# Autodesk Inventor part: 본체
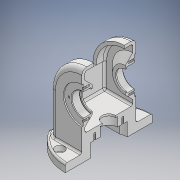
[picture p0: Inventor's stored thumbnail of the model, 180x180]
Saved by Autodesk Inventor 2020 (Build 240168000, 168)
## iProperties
Created: 2024-08
Part Number: 본체
Material: 일반
Document SubType Name: Modeling
Designer: 1강의실14
Density: 1 g/cm^3
Appearance: 기본값
Author: 1강의실14
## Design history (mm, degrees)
sketch "스케치1"
  geometry: L1 (-51, 0)-(-51, -81); L2 (-51, -81)-(51, -81); L3 (51, -81)-(51, 0); A1 r 51 centre (0, 0) between (-51, 0) and (51, 0); 1 further point
  constraints: 6 end point, 2 point on circle, 1 centre point, 1 coincident, 1 perpendicular, 1 tangent, 1 vertical
  dimensions: "d0" = 102 diameter of A1; "d1" = 81 distance of L1.start L1.end; "d2" = 102 distance of L1.end L2.end; "d3" = 81 distance from line of L2 point (0, 0)
extrude "돌출1" new body sketch "스케치1" stored distance "d4" = 88; taper "d5" = 0 deg
sketch "스케치2"
  geometry: L1 (51, 25)-(0, 25); L2 (0, 25)-(0, -25); L3 (0, -25)-(51, -25); L4 (51, -25)-(51, 25); L5 (-10.2, 0)-(61.2, 0) reference; 1 further point
  constraints: 8 end point, 2 parallel, 1 horizontal, 1 perpendicular, 1 other
  dimensions: "d6" = 51 distance of L3.end L2.end; "d7" = 50 distance of L2.end L1.end; "d8" = 0 distance from line of point (0, 0) L2
extrude "돌출2" cut sketch "스케치2" extent not by distance; stored distance "d9" = 51; taper "d10" = 0 deg
sketch "스케치3"
  geometry: C1 r 30 at (0, 0); C2 r 18.5 at (0, 0); C3 r 16 at (0, 0); 1 further point
  constraints: 3 centre point, 3 coincident
  dimensions: "d11" = 60 diameter of C1; "d12" = 37 diameter of C2; "d13" = 32 diameter of C3
extrude "돌출3" cut sketch "스케치3" distance "d14" = 2; taper "d15" = 0 deg
extrude "돌출4" cut sketch "스케치3" distance "d16" = 15; taper "d17" = 0 deg
extrude "돌출5" cut sketch "스케치3" extent not by distance; stored distance "d18" = 0; taper "d19" = 0 deg
sketch "스케치4"
  geometry: C1 r 30 at (0, 0); C2 r 30 at (0, 0) reference; C3 r 18.5 at (0, 0); 1 further point
  constraints: 2 centre point, 2 coincident
  dimensions: "d20" = 60 diameter of C1; "d21" = 37 diameter of C3
extrude "돌출6" cut sketch "스케치4" distance "d22" = 2; taper "d23" = 0 deg
extrude "돌출7" cut sketch "스케치4" distance "d24" = 15; taper "d25" = 0 deg
node "작업 평면1"
sketch "스케치5"
  geometry: L1 (46, -39)-(-41, -39); L2 (-41, -39)-(-41, 39); L3 (-41, 39)-(46, 39); L4 (46, 39)-(46, -39); L5 (51, -44)-(51, -25) reference; L6 (51, -44)-(51, 43.976); L7 (46, 0)-(0, 0); L8 (33.5, -39)-(33.5, -27); L9 (0, -25)-(51, -25) reference; L10 (33.5, -27)-(-35.015, -27); L11 (-33.5, -39)-(-21.5, -27); L12 (-33.5, -39)-(-7.367, -39); L13 (33.5, 39)-(33.5, 27); L14 (33.5, 27)-(-29.081, 27); L15 (-33.5, 39)-(-21.5, 27); L16 (-33.5, 39)-(-9.579, 39); L17 (33.5, 39)-(10.052, 15.552); L18 (33.5, 39)-(66.661, 39); L19 (33.5, -39)-(10.052, -15.552); L20 (33.5, -39)-(66.661, -39); L21 (0, 0)-(0, 27); L22 (0.5, 27)-(0.5, -27); L23 (-81, -44)-(-81, 44) reference; L24 (0, 25)-(0, 25) reference; L25 (0, 25)-(0, 44) reference; L26 (0, 44)-(0, 44) reference; L27 (0, 44)-(0, 25) reference; L28 (51, 44)-(0, 44) reference; 4 further points
  constraints: 40 end point, 10 point on line, 7 horizontal, 6 perpendicular, 2 equal length, 2 parallel, 1 midpoint, 1 vertical
  dimensions: "d27" = 5 distance between parallel lines of L4 L6; "d28" = 78 distance between parallel lines of L3 L1; "d29" = 12 distance of L8.start L8.end; "d30" = 33.5 distance from line of L7.end L8; "d32" = 45 deg angle of L12 L11; "d33" = 12 distance of L13.start L13.end; "d34" = 45 deg angle of L15 L16; "d35" = 33.5 distance from line of L7.end L13; "d36" = 135 deg angle of L17 L18; "d37" = 135 deg angle of L20 L19; "d38" = 33.5 horizontal distance of L11.start L7.end; "d39" = 33.5 horizontal distance of L15.start L7.end; "d88" = 40 distance between parallel lines of L23 L2; "d89" = 45.5 distance between parallel lines of L22 L4; "d145" = 33.16071 distance of L8.start L20.end; "d146" = 33.16071 distance of L13.start L18.end; "d147" = 5 distance between parallel lines of L3 L28 (derived)
  node "투영된 루프1"
sketch "스케치6"
  geometry: L1 (-72, 0)-(-16, 0); L2 (-16, 0)-(-16, 19); L3 (-16, 19)-(-72, 19); L4 (-72, 19)-(-72, 0); L5 (-88, 0)-(0, 0) reference; L6 (-69, 81)-(-19, 81) reference; 5 further points
  constraints: 8 end point, 4 midpoint, 2 parallel, 1 coincident, 1 horizontal, 1 perpendicular, 1 vertical alignment
  dimensions: "d40" = 56 distance of L3.end L2.end; "d41" = 19 distance of L2.end L1.end
extrude "돌출8" cut sketch "스케치6" extent not by distance; stored distance "d42" = 0; taper "d43" = 0 deg
node "작업 평면2"
sketch "스케치7"
  geometry: C1 r 30 at (0, 0); C2 r 14 at (0, 0); C3 r 11 at (0, 0); 1 further point
  constraints: 3 centre point, 3 coincident
  dimensions: "d45" = 60 diameter of C1; "d46" = 28 diameter of C2; "d47" = 22 diameter of C3
extrude "돌출9" cut sketch "스케치7" distance "d48" = 22; taper "d49" = 0 deg
extrude "돌출10" cut sketch "스케치7" distance "d50" = 37; taper "d51" = 0 deg
extrude "돌출11" cut sketch "스케치7" extent not by distance; stored distance "d52" = 69.381; taper "d53" = 0 deg
sketch "스케치9"
  geometry: C1 r 11 at (0, 0) reference; C2 r 71 at (0, 0); 1 further point
  constraints: 1 centre point, 1 coincident
  dimensions: "d55" = 142 diameter of C2
extrude "돌출12" join sketch "스케치9" distance "d56" = 13; taper "d57" = 0 deg
sketch "스케치8"
  geometry: L1 (-51, -81)-(51, -81) reference; 2 further points
  constraints: 1 vertical alignment, 1 other
  dimensions: "d54" = 30 distance from line of L1 point (0, -51)
sketch "스케치10"
  geometry: L1 (-80, 28)-(80, 28); L2 (80, 28)-(80, -28); L3 (80, -28)-(-80, -28); L4 (-80, -28)-(-80, 28); L5 (-80, 28)-(80, -28); L6 (80, 28)-(-80, -28); 1 further point
  constraints: 12 end point, 2 midpoint, 2 parallel, 1 horizontal, 1 perpendicular
  dimensions: "d58" = 56 distance of L1.end L2.end; "d59" = 80 distance from line of point (0, 0) L2
extrude "돌출13" cut sketch "스케치10" distance "d60" = 13; taper "d61" = 0 deg
extrude "돌출14" cut sketch "스케치7" distance "d62" = 22; taper "d63" = 0 deg
sketch "스케치11"
  geometry: C1 r 7.5 at (25, 55); C2 r 4.5 at (25, 55); C3 r 7.5 at (-25, 55); C4 r 4.5 at (-25, 55); C5 r 7.5 at (25, -55); C6 r 4.5 at (25, -55); C7 r 7.5 at (-25, -55); C8 r 4.5 at (-25, -55); 1 further point
  constraints: 8 centre point, 4 coincident, 2 horizontal alignment, 2 vertical alignment
  dimensions: "d64" = 15 diameter of C1; "d65" = 9 diameter of C2; "d66" = 15 diameter of C3; "d67" = 9 diameter of C4; "d68" = 15 diameter of C5; "d69" = 9 diameter of C6; "d70" = 15 diameter of C7; "d71" = 9 diameter of C8; "d72" = 110 distance of C5.centre C1.centre; "d73" = 50 distance of C3.centre C1.centre; "d74" = 55 vertical distance of point (0, 0) C1.centre; "d75" = 25 horizontal distance of point (0, 0) C3.centre
extrude "돌출15" cut sketch "스케치11" distance "d76" = 8.8; taper "d77" = 0 deg
extrude "돌출16" cut sketch "스케치11" extent not by distance; stored distance "d78" = 0; taper "d79" = 0 deg
revolve "회전2" stored, may be unused: angle "d90" = 180 deg
sketch "스케치13" dims "d173" = 92
  geometry: L1 (-46, -0.5)-(46, -0.5); L2 (46, -0.5)-(46, -41.5); L3 (46, -41.5)-(-46, -41.5); L4 (-46, -41.5)-(-46, -0.5); L5 (65.246, -81.5)-(-65.246, -81.5) reference; L6 (-51, -68.5)-(-51, -0.5) reference; L7 (-45.497, -0.5)-(-51, -0.5) reference; L8 (-45.497, -0.5)-(-51, -0.5) reference; C1 r 18.5 at (0, -0.5); C2 r 33 at (0, -0.5); A1 r 51 centre (0, -0.5) between (51, -0.5) and (-51, -0.5) reference; A2 r 51 centre (0, -0.5) between (51, -0.5) and (-51, -0.5) reference; 5 further points
  constraints: 8 end point, 4 coincident, 2 centre point, 2 parallel, 1 horizontal, 1 horizontal alignment, 1 midpoint, 1 perpendicular, 2 other
  dimensions: "d93" = 40 distance between parallel lines of L5 L3; "d95" = 37 diameter of C1; "d96" = 66 diameter of C2
extrude "돌출17" cut sketch "스케치13" stored distance "d97" = 10; taper "d98" = 0 deg
sketch "스케치14"
  geometry: L1 (-5, 83)-(-5, 67) reference; L2 (97, -5)-(-5, -5); L3 (-5, -5)-(-5, 83); L4 (-5, 83)-(97, 83); L5 (97, 83)-(97, -5); L6 (97, -5)-(-5, 83); L7 (-5, -5)-(97, 83); 2 further points
  constraints: 12 end point, 2 midpoint, 2 parallel, 1 horizontal, 1 perpendicular
extrude "돌출18" join sketch "스케치14" stored distance "d99" = 13; taper "d100" = 0 deg
extrude "돌출19" cut sketch "스케치7" distance "d101" = 37; taper "d102" = 0 deg
extrude "돌출20" cut sketch "스케치7" extent not by distance; stored distance "d103" = 40; taper "d104" = 0 deg
feature "엠보싱1" dims "d11" = 60, "d12" = 37, "d13" = 32, "d105" = 0.5, "d106" = 0
sketch "스케치15"
  geometry: L1 (0, 0)-(0, 23)
  constraints: 2 end point, 1 vertical
  dimensions: "d107" = 23 distance of L1.start L1.end
hole "구멍1" sketch "스케치15" at (0, 23) diameter "d108" = 3.242; stored, may be unused: countersink angle "d112" = 90 deg, drill point angle "d114" = 118 deg; dims "d109" = 8, "d110" = 4, "d111" = 2, "d113" = 10
sketch "스케치17"
  geometry: L1 (0, 0)-(0, 23)
  constraints: 2 end point, 1 vertical
  dimensions: "d129" = 23 distance of L1.start L1.end
hole "구멍3" sketch "스케치17" at (0, 23) diameter "d130" = 3.242; stored, may be unused: countersink angle "d134" = 90 deg, drill point angle "d136" = 118 deg; dims "d131" = 8, "d132" = 4, "d133" = 2, "d135" = 10
fillet "모깎기1" dims "d140" = 6
fillet "모깎기2" dims "d141" = 8
fillet "모깎기3" dims "d142" = 3
fillet "모깎기4" dims "d143" = 0.3
fillet "모깎기5" dims "d144" = 3
sketch "스케치18"
  geometry: L1 (112, 45)-(102, 45); L2 (102, 45)-(102, 5); L3 (102, 5)-(112, 5); L4 (112, 5)-(112, 45); L5 (112, 45)-(102, 5); L6 (102, 45)-(112, 5); L7 (61.77, 53)-(102, 53) reference; L8 (102, -3)-(102, 53) reference; L9 (61.77, -3)-(102, -3) reference; L10 (51, 25)-(51, -52.36); L11 (0, 45)-(0, 5); L12 (-10, 5)-(-10, 45); L13 (-10, 45)-(0, 45); L14 (0, 5)-(-10, 5); A1 r 30 centre (51, 25) between (61.77, -3) and (61.77, 53) reference; 3 further points
  constraints: 22 end point, 4 symmetric about line, 3 midpoint, 2 parallel, 1 horizontal, 1 horizontal alignment, 1 perpendicular, 1 vertical
  dimensions: "d148" = 40 distance of L3.end L1.start; "d150" = 61 distance from line of point (51, 25) L4; "d151" = 0 distance between parallel lines of L8 L2
extrude "돌출21" join sketch "스케치18" distance "d152" = 20; taper "d153" = 0 deg
fillet "모깎기6" dims "d154" = 3
sketch "스케치19"
  geometry: L1 (-46, -25)-(8, -25); L2 (8, -25)-(8, -12)
  constraints: 4 end point, 1 horizontal, 1 perpendicular
  dimensions: "d155" = 54 distance of L1.start L1.end; "d156" = 13 distance of L1.end L2.end
hole "구멍4" sketch "스케치19" at (8, -12) diameter "d157" = 3.242; stored, may be unused: countersink angle "d161" = 90 deg, drill point angle "d163" = 118 deg; dims "d158" = 8, "d159" = 4, "d160" = 2, "d162" = 10
fillet "모깎기7" dims "d170" = 3
fillet "모깎기8" dims "d174" = 3
fillet "모깎기9" dims "d175" = 3
fillet "모깎기10" dims "d176" = 3
sketch "스케치20"
  geometry: L1 (0, 0)-(0, 23); C1 r 16 at (0, 0) reference; 1 further point
  constraints: 2 end point, 1 vertical
  dimensions: "d177" = 23 distance of L1.start L1.end
hole "구멍5" sketch "스케치20" at (0, 23) diameter "d178" = 3.242; stored, may be unused: countersink angle "d182" = 90 deg, drill point angle "d184" = 118 deg; dims "d179" = 8, "d180" = 4, "d181" = 2, "d183" = 10
chamfer "모따기1" distance "d188" = 1; stored, may be unused: second distance "d189" = 2, angle "d190" = 45 deg
fillet "모깎기11" dims "d191" = 3
feature "분할1"
node "솔리드1"
pattern_circular "원형 패턴1" dims angle "d116" = 360 deg
pattern_circular "원형 패턴3" dims angle "d138" = 360 deg
pattern_linear "직사각형 패턴1" dims "d166" = 26
pattern_linear "직사각형 패턴2" dims "d169" = 108
pattern_circular "원형 패턴4" dims angle "d186" = 360 deg
node "투영된 루프2"
node "투영된 루프3"
node "투영된 루프4"
feature "A9D066F2-1C7D-4E18-AEED-F7BC21143FA4" dims "d108" = 3.242, "d109" = 8, "d110" = 4, "d111" = 2, "d112" = 90 deg, "d113" = 10, "d114" = 118 deg
other parameters: "d26" = -31, "d44" = -81
